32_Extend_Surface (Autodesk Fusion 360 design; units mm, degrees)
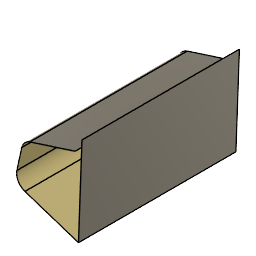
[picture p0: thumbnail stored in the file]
part number: 2026-07-17-16-02-36-355
sketch "Sketch1" plane through (0, 0, 0) normal (0, 1, 0) x axis (1, 0, 0)
  line L1 (-43.2638, -6.1805) -> (-0.3987, -19.9372)
  line L2 (-50.4412, 26.7159) -> (-43.2638, -6.1805)
  line L3 (2.3925, 44.0613) -> (-50.4412, 26.7159)
extrude "Extrude1" new body distance 65
fillet "Fillet1" radius 10
step "SurfaceRuled" ruledDistance 75 ruledAngle -20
